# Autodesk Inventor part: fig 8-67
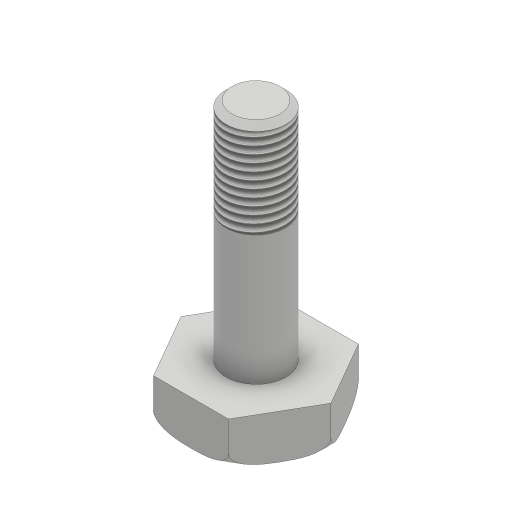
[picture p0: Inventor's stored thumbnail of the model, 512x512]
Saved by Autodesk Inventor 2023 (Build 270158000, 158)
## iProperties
Created: 2016-04
Part Number: fig 8-67
Material: Generic
Document SubType Name: Modeling
Designer: Sandeep
Density: 1 g/cm^3
Appearance: Default
Author: Sandeep
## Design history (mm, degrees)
sketch "Sketch1"
  geometry: C1 r 25 at (0, 0); 1 further point
  constraints: 1 centre point, 1 coincident
  dimensions: "d0" = 50 diameter of C1
extrude "Extrusion1" new body sketch "Sketch1" distance "d1" = 15; taper "d2" = 0 deg
fillet "Fillet1" dims "d3" = 5
sketch "Sketch2"
  geometry: L1 (12.5, 21.651)-(25, 0); L2 (25, 0)-(12.5, -21.651); L3 (12.5, -21.651)-(-12.5, -21.651); L4 (-12.5, -21.651)-(-25, 0); L5 (-25, 0)-(-12.5, 21.651); L6 (-12.5, 21.651)-(12.5, 21.651); 3 further points
  constraints: 12 end point, 1 coincident, 1 horizontal, 15 other
extrude "Extrusion2" cut sketch "Sketch2" distance "d4" = 32.5; taper "d5" = 0 deg
sketch "Sketch3"
  geometry: C1 r 10 at (0, 0); 1 further point
  constraints: 1 centre point, 1 coincident
  dimensions: "d6" = 20 diameter of C1
extrude "Extrusion3" join sketch "Sketch3" distance "d7" = 75; taper "d8" = 0 deg
chamfer "Chamfer1" distance "d9" = 2; stored, may be unused: second distance "d10" = 2, angle "d11" = 45 deg
thread "Thread1" dims "d12" = 30, "d13" = 0
body "Solid1"
